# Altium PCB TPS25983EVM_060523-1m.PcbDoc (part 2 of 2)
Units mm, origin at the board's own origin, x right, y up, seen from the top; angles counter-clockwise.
Board outline 76.2 x 78.74 mm, 4 copper layers (L1-Top Layer, L2-GND1, L3-PWR/SIG, L4-Bottom Layer), stack 1.554 mm thick; 100 components, 38 nets, 213 pads, 280 vias.
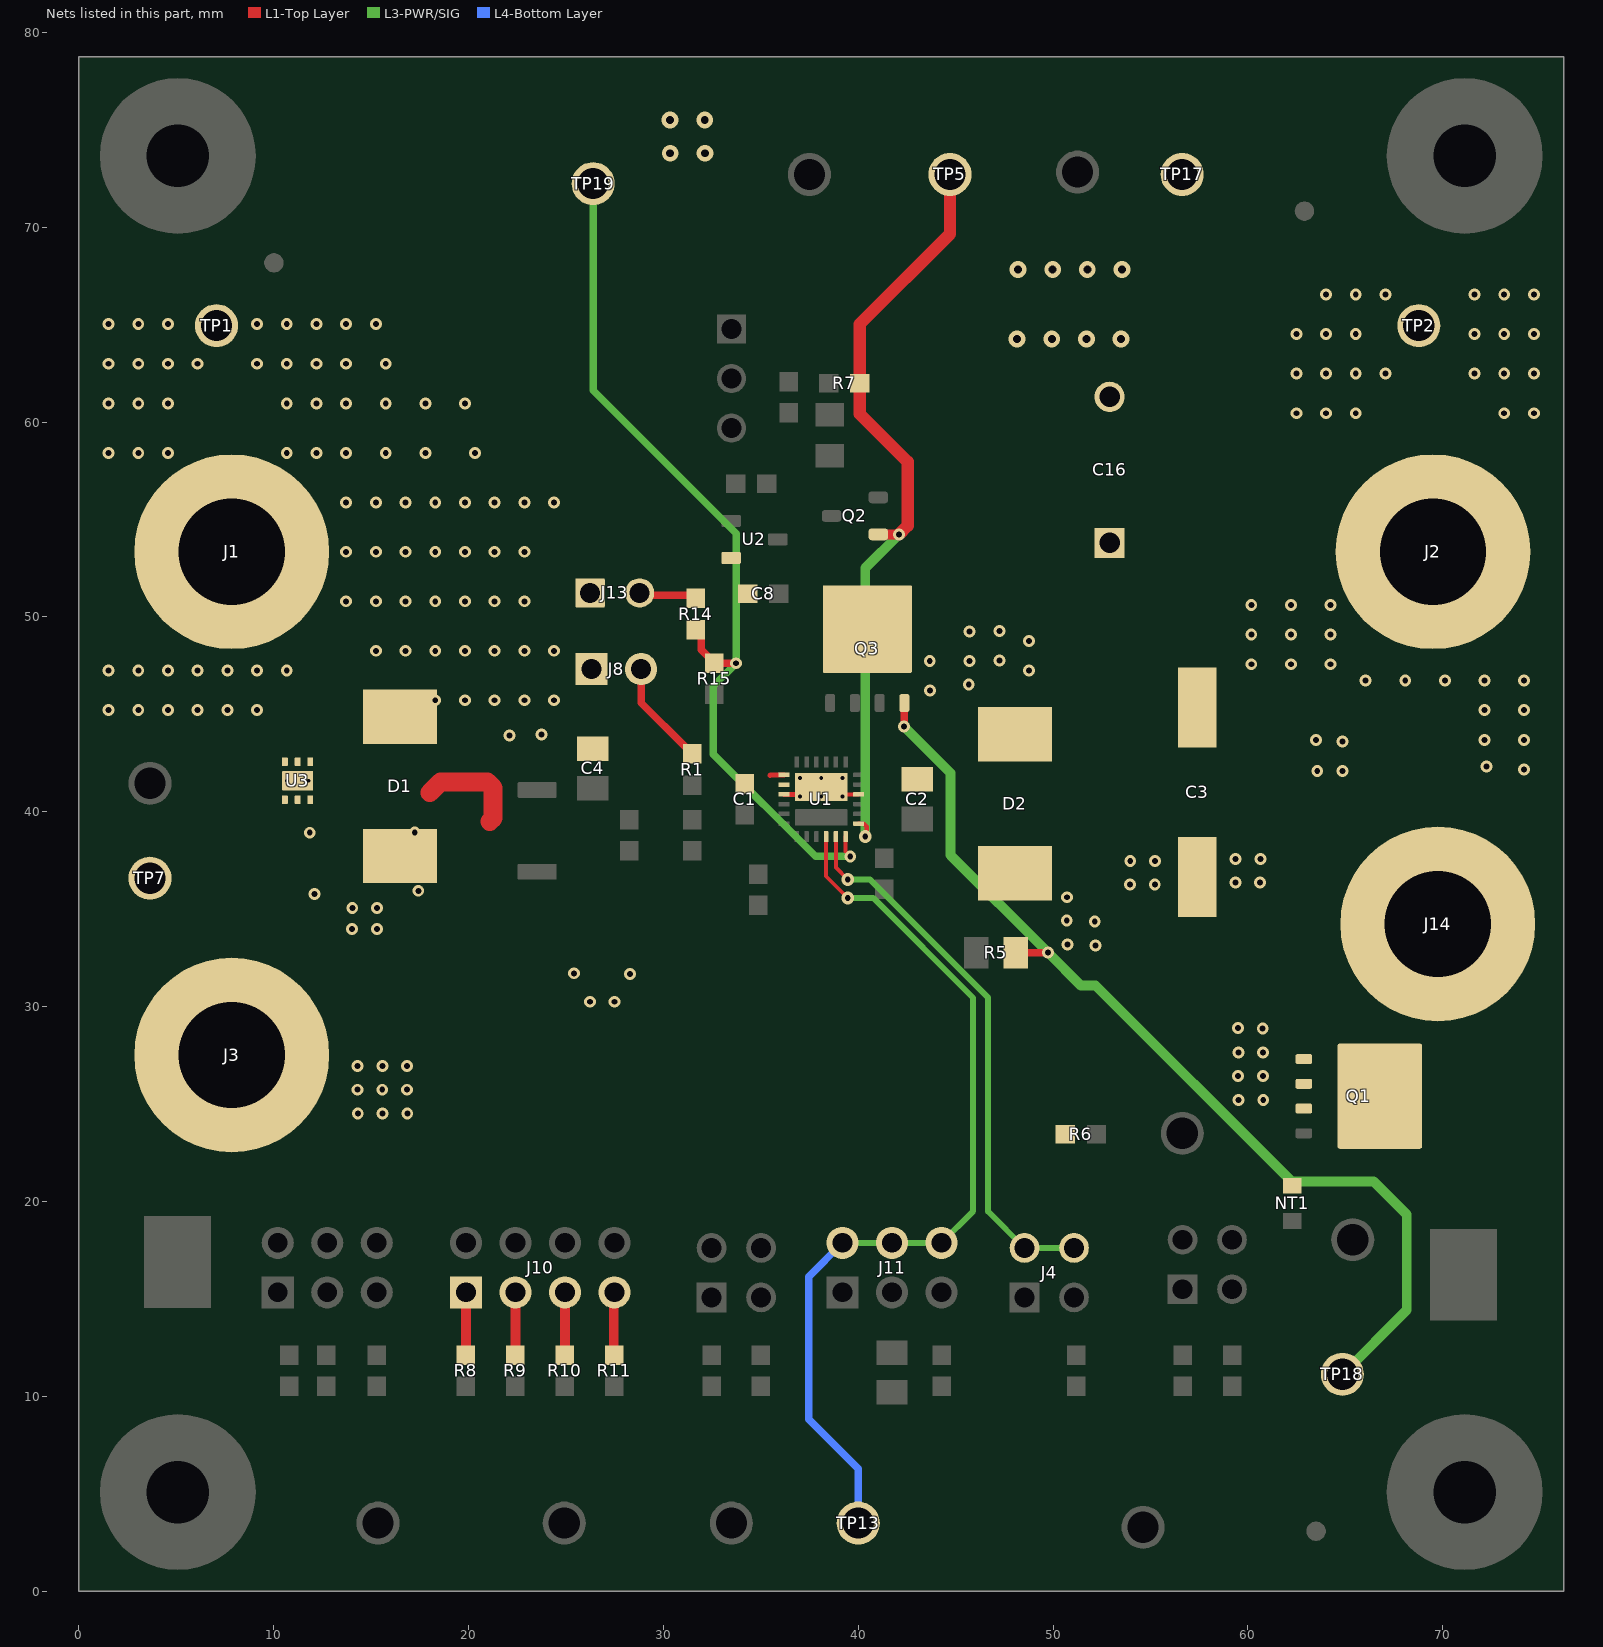
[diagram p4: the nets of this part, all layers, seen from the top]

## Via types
v1: diameter 0.61, hole 0.305, L1-Top Layer to L4-Bottom Layer, tented both sides, 249 vias
v2: diameter 0.864, hole 0.406, L1-Top Layer to L4-Bottom Layer, 12 vias
v3: diameter 0.5, hole 0.2, L1-Top Layer to L4-Bottom Layer, 11 vias
v4: diameter 0.66, hole 0.305, L1-Top Layer to L4-Bottom Layer, tented both sides, 8 vias

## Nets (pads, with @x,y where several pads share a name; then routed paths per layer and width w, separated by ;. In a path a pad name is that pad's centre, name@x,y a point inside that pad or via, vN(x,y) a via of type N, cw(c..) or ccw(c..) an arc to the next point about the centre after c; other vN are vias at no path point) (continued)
NetJ8_2: J8.2 R1.2 | length 5.5
  L1-Top Layer w0.381: J8.2@28.854,47.32 28.854,45.58 31.161,43.273 31.186,43.273 31.471,42.989 R1.2@31.471,42.964
NetJ10_1: J10.1 R8.2 | length 3.2
  L1-Top Layer w0.508: R8.2@19.864,12.108 J10.1@19.864,15.334
NetJ10_3: J10.3 R9.2 | length 3.5
  L1-Top Layer w0.508: R9.2@22.326,11.909 22.404,11.987 R9.2@22.404,12.108 J10.3@22.404,15.334
NetJ10_5: J10.5 R10.2 | length 3.1
  L1-Top Layer w0.508: J10.5@24.944,15.165 24.949,15.16 24.949,12.108 R10.2@24.949,12.079
NetJ10_7: J10.7 R11.2 | length 3.1
  L1-Top Layer w0.508: R11.2@27.448,12.079 27.448,12.108 27.448,15.129 J10.7@27.484,15.165
NetJ13_2: J13.2 R14.2 | length 3
  L1-Top Layer w0.381: J13.2@28.778,51.232 28.906,51.104 31.491,51.104 R14.2@31.648,50.947
NetJ14_1: J14.1 Q1.5 Q1.6 Q1.7 Q1.8 Q1.9
NetQ2_1: Q2.1 R7.1 TP5.1 U1.13 | length 39.9
  L1-Top Layer w0.229: U1.13@40.013,39.39 40.284,39.39 40.424,39.25 40.424,38.791 v4(40.357,38.724)
  L1-Top Layer w0.508: Q2.1@41.03,54.232 v1(42.086,54.232)
  L1-Top Layer w0.635: v1(42.086,54.232) 42.538,54.683 42.538,57.953 40.078,60.414 R7.1@40.078,61.981 40.078,65.024 44.707,69.653 TP5.1@44.707,72.707
  L3-PWR/SIG w0.508: v4(40.357,38.724) 40.357,52.503 v1(42.086,54.232)
NetQ3_4: Q3.4 R5.2 TP18.1 | length 51.1
  L1-Top Layer w0.381: v1@42.367,44.351 Q3.4@42.367,45.578 ; R5.2@48.082,32.766 v1(49.733,32.766)
  L3-PWR/SIG w0.508: v1(42.342,44.376) 44.729,41.988 44.729,37.77 v1(49.733,32.766) 51.416,31.083 52.184,31.083 62.236,21.031 66.446,21.031 68.148,19.329 68.148,14.427 TP18.1@64.846,11.125
NetR14_1: R14.1 R15.2 TP19.1 U1.12 | length 46.4
  L1-Top Layer w0.203: U1.12@39.35,38.727 39.35,37.95 v1(39.589,37.711)
  L1-Top Layer w0.381: R14.1@31.648,49.347 31.932,49.062 31.932,48.317 32.603,47.645 R15.2@32.603,47.62 v1(33.734,47.62)
  L3-PWR/SIG w0.381: TP19.1@26.391,72.238 26.391,61.62 33.734,54.277 v1(33.734,47.62) 32.566,46.452 32.566,42.949 37.803,37.711 v1(39.589,37.711)
NRETRY: J4.2 J4.4 U1.11 | length 28.3
  L1-Top Layer w0.203: U1.11@38.85,38.727 38.85,37.141 v4(39.46,36.53)
  L3-PWR/SIG w0.305: v4(39.46,36.53) 40.593,36.53 46.665,30.457 46.665,19.48 J4.2@48.533,17.612 J4.4@51.073,17.612
PGND: C3.2 C16.2 D1.2 D2.2 J3.1 NT1.2 Q1.1 Q1.2 Q1.3 R6.1 TP7.1 TP17.1 U3.1 U3.2 U3.3 U3.7@11.226,41.591 | length 5.4
  L1-Top Layer w0.965: 18.009,40.97 18.567,41.529 19.237,41.529 19.787,41.529 20.337,41.529 20.955,41.529 21.26,41.224 21.26,39.675 21.082,39.497
  other v1: 14.313,24.504 15.583,24.504 16.853,24.504 59.514,25.208 60.784,25.208 14.298,25.733 15.568,25.733 16.838,25.733 59.498,26.437 60.768,26.437 14.307,26.944 15.577,26.944 16.847,26.944 59.507,27.647 60.777,27.647 60.757,28.88 59.487,28.905 26.224,30.249 27.494,30.249 28.288,31.665 25.412,31.708 52.176,33.128 50.738,33.187 14.022,33.979 15.292,33.979 52.137,34.363 50.699,34.421 14.031,35.063 15.301,35.063 50.71,35.611 12.091,35.776 17.419,35.941 53.949,36.268 55.219,36.268 59.356,36.362 60.626,36.362 53.958,37.479 55.228,37.479 59.365,37.572 60.635,37.572 11.848,38.923 17.236,38.938
  other v2: 48.154,64.266 49.932,64.266 51.71,64.266 53.488,64.266 48.199,67.83 49.977,67.83 51.755,67.83 53.533,67.83 30.347,73.794 32.125,73.794 30.343,75.503 32.121,75.503
  other v3: 10.676,41.591 11.776,41.591
RETRY_DLY: J11.2 J11.4 J11.6 TP13.1 U1.10 | length 46.7
  L1-Top Layer w0.203: U1.10@38.35,38.727 38.35,36.688 v4(39.46,35.578)
  L3-PWR/SIG w0.305: J11.2@39.192,17.874 J11.4@41.732,17.874 J11.6@44.272,17.874 45.898,19.5 45.898,30.442 40.762,35.578 v4(39.46,35.578)
  L4-Bottom Layer w0.381: J11.2@39.192,17.874 37.455,16.136 37.455,8.825 39.999,6.28 TP13.1@39.999,3.49
VIN: C1.1 C4.1 C8.1 D1.1 J1.1 J8.1 J13.1 TP1.1 U1.1 U1.2 U1.3 U1.16 U1.25 U2.2 U3.4 U3.5 U3.6 | length 6.7
  L1-Top Layer w0.203: U1.25@38.861,40.89 U1.16@40.013,40.89
  L1-Top Layer w0.254: 35.458,41.859 35.489,41.89 U1.1@36.187,41.89 ; U1.3@36.187,40.89 37.725,40.89 U1.25@38.1,41.265 ; U1.25@36.93,41.265 U1.25@38.1,41.265 ; U1.25@36.937,41.758 37.607,41.758 U1.25@38.1,41.265 ; U1.25@38.735,41.016 U1.25@38.861,40.89
  other v1: 22.098,43.917 23.749,43.967 1.524,45.212 3.048,45.212 4.572,45.212 6.096,45.212 7.62,45.212 9.144,45.212 18.288,45.72 19.812,45.72 21.336,45.72 22.86,45.72 24.384,45.72 1.524,47.244 3.048,47.244 4.572,47.244 6.096,47.244 7.62,47.244 9.144,47.244 10.668,47.244 15.24,48.26 16.764,48.26 18.288,48.26 19.812,48.26 21.336,48.26 22.86,48.26 24.384,48.26 13.716,50.8 15.24,50.8 16.764,50.8 18.288,50.8 19.812,50.8 21.336,50.8 22.86,50.8 13.716,53.34 15.24,53.34 16.764,53.34 18.288,53.34 19.812,53.34 21.336,53.34 22.86,53.34 13.716,55.88 15.24,55.88 16.764,55.88 18.288,55.88 19.812,55.88 21.336,55.88 22.86,55.88 24.384,55.88 1.524,58.42 3.048,58.42 4.572,58.42 10.668,58.42 12.192,58.42 13.716,58.42 15.748,58.42 17.78,58.42 20.32,58.42 1.524,60.96 3.048,60.96 4.572,60.96 10.668,60.96 12.192,60.96 13.716,60.96 15.748,60.96 17.78,60.96 19.812,60.96 1.524,62.992 3.048,62.992 4.572,62.992 6.096,62.992 9.144,62.992 10.668,62.992 12.192,62.992 13.716,62.992 15.748,62.992 1.524,65.024 3.048,65.024 4.572,65.024 9.144,65.024 10.668,65.024 12.192,65.024 13.716,65.024 15.24,65.024
  other v3: 37,40.79 38.1,40.79 39.2,40.79 37,41.74 38.1,41.74 39.2,41.74
VOUT: C2.1 C3.1 C16.1 D2.1 J2.1 Q3.5 Q3.6 Q3.7 Q3.8 Q3.9 TP2.1
  other v1: 64.846,42.088 63.555,42.099 74.168,42.164 72.234,42.313 64.846,43.612 63.5,43.688 72.136,43.688 74.168,43.688 72.136,45.212 74.168,45.212 43.688,46.228 45.669,46.533 66.04,46.736 68.072,46.736 70.104,46.736 72.136,46.736 74.168,46.736 48.768,47.244 60.172,47.57 62.204,47.57 64.236,47.57 43.667,47.728 45.699,47.728 47.244,47.752 48.768,48.768 60.172,49.094 62.204,49.094 64.236,49.094 45.699,49.252 47.244,49.276 60.172,50.618 62.204,50.618 64.236,50.618 62.484,60.452 64.008,60.452 65.532,60.452 73.152,60.452 74.676,60.452 62.484,62.484 64.008,62.484 65.532,62.484 67.056,62.484 71.628,62.484 73.152,62.484 74.676,62.484 62.484,64.516 64.008,64.516 65.532,64.516 71.628,64.516 73.152,64.516 74.676,64.516 64.008,66.548 65.532,66.548 67.056,66.548 71.628,66.548 73.152,66.548 74.676,66.548
pads on no net: FID1.1 FID2.1 FID3.1 H1.1 H2.1 H3.1 H4.1 H5.0 H6.0 H7.0 H8.0 SH-J1.0 SH-J2.0 SH-J3.0 SH-J4.0 SH-J5.0 SH-J6.0 SH-J7.0 U3.7@10.776,41.591 U3.7@11.676,41.591

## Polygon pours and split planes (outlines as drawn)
PGND on L1-Top Layer "L1-TOP_LAYER_PGND_P100" (solid, remove dead copper, pour order 100): 64.153,68.459 48.095,52.401 39.334,52.401 37.784,53.952 37.784,58.635 36.221,60.198 22.885,60.198 14.834,68.326 2.094,68.284 0.864,69.514 0.864,73 5.639,77.749 10.338,77.749 71.196,77.749 75.558,73.388 75.558,69.593 74.424,68.459
PGND on L1-Top Layer "L1-TOP_LAYER_PGND_P098" (solid, remove dead copper, pour order 98): 2.646,20.389 1.055,21.981 1.055,41.14 1.437,41.545 21.793,41.545 21.793,33.463 23.023,32.233 43.885,32.233 44.876,33.223 44.876,40.044 45.15,40.339 63.437,40.339 64.016,39.757 64.016,21.07 63.386,20.389
NetJ14_1 on L1-Top Layer "NONET_L01_P-001" (solid, pour order 125): 64.57,20.253 64.57,39.32 65.681,40.431 74.195,40.431 75.686,38.94 75.686,21.429 74.371,20.114 64.709,20.114
GND on L1-Top Layer "L1-TOP_LAYER_GND_P092" (solid, remove dead copper, pour order 92): 61.476,19.593 61.666,19.403 62.954,19.403 63.142,19.593 69.345,19.593 72.436,19.593 74.286,19.593 75.526,18.391 75.526,9.107 75.526,6.904 68.961,0.432 6.147,0.432 0.7,5.879 0.734,10.008 0.734,14.915 0.715,18.158 2.15,19.593
GND on L1-Top Layer "L1-TOP_LAYER_GND_P088" (solid, remove dead copper, pour order 88): 33.167,40.514 32.598,39.945 32.609,39.391 31.804,38.586 27.584,38.586 27.229,38.941 27.229,41.758 27.127,41.859 25.552,41.859 25.326,41.633 25.326,38.989 24.92,38.586 22.428,38.586 22.428,33.68 23.241,32.868 43.544,32.868 44.174,33.498 44.174,40.213 44.042,40.335 42.871,40.335 36.703,40.335 36.524,40.514
VIN on L1-Top Layer "L1-TOP_LAYER_VIN_P090" (solid, remove dead copper, pour order 90): 33.432,53.83 32.996,53.83 32.147,54.678 32.147,55.115 32.147,57.444 30.501,59.09 22.647,59.09 13.79,67.947 1.488,67.947 1.087,67.474 1.087,43.179 1.975,42.291 32.026,42.291 32.183,42.134 32.183,41.404 32.352,41.235 35.878,41.235 35.878,48.668 35.878,49.686 34.865,50.699 34.865,52.397 34.112,53.15
GND on L1-Top Layer "M1 Board Outline-No Net" (solid, pour order 104): 34.591,54.129 35.463,53.258 35.463,50.781 35.613,50.63 36.635,50.63 37.02,51.015 37.02,57.672 36.712,57.979 35.216,57.979 34.941,57.979 34.591,57.629
DVOUT on L1-Top Layer "NONET_L-01_P-001" (solid, remove dead copper, pour order 121): 41.187,46.154 37.639,46.154 36.512,45.027 36.512,42.497 36.743,42.266 39.496,42.266 39.719,42.043 39.719,41.258 39.766,41.211 40.248,41.211 40.326,41.289 40.326,42.934 41.371,43.979 41.371,45.97
VOUT on L1-Top Layer "L1-TOP_LAYER_VOUT_P086" (solid, remove dead copper, pour order 86): 41.69,42.801 43.34,44.451 43.34,46.673 42.914,47.099 38.255,47.099 37.614,47.74 37.614,51.061 38.144,51.591 48.361,51.591 64.534,67.765 74.694,67.765 75.123,67.365 75.123,42.338 73.808,41.023 42.062,41.023 41.69,41.395
PGND on L4-Bottom Layer "PWR1-No Net" (solid, pour order 114): 1.025,73.694 1.025,5.668 6.007,0.686 69.977,0.686 75.408,6.117 75.408,73.605 70.759,78.254 5.584,78.254
VIN on L4-Bottom Layer "L4-BOTTOM_LAYER_VIN_P106" (solid, remove dead copper, pour order 106): 29.128,52.89 14.2,67.818 1.016,67.818 1.016,40.564 39.377,40.564 39.498,40.684 39.498,40.964 39.498,41.604 39.498,46.388 32.995,52.89
GND on L4-Bottom Layer "M1 Board Outline-No Net" (solid, pour order 112): 39.471,39.935 39.813,39.593 39.813,38.223 40.529,37.507 40.529,34.372 38.956,32.788 24.303,32.788 23.58,33.512 23.58,39.332 24.165,39.917 36.842,39.917 36.861,39.935
VOUT on L4-Bottom Layer "GND_L01_P-001" (solid, remove dead copper, pour order 110): 41.656,45.665 41.656,49.922 42.438,50.673 47.427,50.673 49.906,48.194 49.906,42.447 49.191,41.732 45.589,41.732
PGND on L3-PWR/SIG "NONET_L-01_P-001" (solid, remove dead copper, pour order 123): 40.61,61.121 40.61,55.442 40.985,55.067 46.783,55.067 47.972,56.256 58.046,56.256 60.361,58.571 60.361,61.866 57.128,65.099 57.128,68.582 59.902,71.356 59.902,74.985 59.11,75.778 54.834,75.778 54.062,75.006 54.062,70.897 52.227,69.062 48.551,69.062
VOUT on L3-PWR/SIG "PWR1-No Net" (solid, pour order 108): 58.365,55.118 48.136,55.118 43.27,50.253 43.27,44.668 46.773,41.148 73.939,41.148 75.184,42.393 75.184,66.726 72.72,69.19 58.903,69.19 57.988,68.275 57.988,65.456 61.354,62.09 61.354,58.108
DVOUT on L3-PWR/SIG "NONET_L-01_P-001" (solid, remove dead copper, pour order 122): 53.332,74.203 51.655,75.88 44.701,75.88 34.851,66.03 34.851,43.797 35.894,42.754 39.085,42.754 39.559,43.227 39.559,61.612 48.239,70.292 52.542,70.292 53.332,71.082
VIN on L3-PWR/SIG "PWR1-No Net" (solid, remove dead copper, pour order 116): 15.176,66.459 1.892,66.459 1.118,65.684 1.118,41.072 1.651,40.538 26.695,40.538 27.483,41.326 27.483,54.153 21.949,59.687
GND on L2-GND1 "PWR1-No Net" (solid, remove dead copper, pour order 120): 6.649,1.041 0.991,6.699 1.025,7.391 1.025,74.101 5.178,78.254 70.759,78.254 75.408,73.605 75.408,6.879 69.571,1.041

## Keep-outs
Keep-Out Layer:
  lines w0.254: 0,0 76.2,0 ; 0,0 0,78.74 ; 0,0 76.2,0 ; 0,0 0,78.74 ; 0,78.74 76.2,78.74 ; 0,78.74 76.2,78.74 ; 76.2,0 76.2,78.74
  text ".Layer_Name" at 9.082,-28.565 h1.52

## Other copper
L1-Top Layer:
  region net GND: 62.96,19.403 61.666,19.403 61.574,19.311 61.574,18.7 61.678,18.596 62.902,18.596 63.009,18.703 63.009,19.354
  region net PGND: 61.599,20.389 62.893,20.389 62.985,20.481 62.985,21.092 62.88,21.196 61.657,21.196 61.549,21.089 61.549,20.439
  region net VIN: 32.183,42.42 32.599,42.836 35.65,42.836 36.529,41.957 39.225,41.957 39.314,41.868 39.314,40.904 39.075,40.665 37.059,40.665 36.957,40.767 32.769,40.767 32.183,41.354
  region net DVOUT: 36.677,42.98 36.806,43.109 39.909,43.109 40.326,42.692 40.326,41.289 40.248,41.211 39.766,41.211 39.719,41.258 39.719,42.043 39.496,42.266 36.743,42.266 36.677,42.332
  region net DVDT: 40.97,40.259 41.097,40.132 41.097,38.329 40.843,38.075 40.843,37.135 40.894,37.084 41.758,37.084 41.808,37.135 41.808,38.176 41.681,38.303 41.681,40.894 41.554,41.021 41.173,41.021 40.665,40.513 39.751,40.513 39.726,40.488 39.726,40.284 39.751,40.259
  region net GND: 35.89,40.513 35.814,40.437 35.814,39.878 35.916,39.776 36.652,39.776 36.754,39.675 36.754,39.319 36.779,39.294 39.421,39.294 39.472,39.345 39.472,39.7 39.548,39.776 40.284,39.776 40.31,39.802 40.31,39.98 40.259,40.03 39.548,40.03 39.421,40.157 36.881,40.157 36.525,40.513
  pour cut-out: 34.612,36.565 35.233,35.944 40.185,35.944 40.533,35.944 41.17,36.582 41.17,38.285 40.245,39.21 40.184,39.149 35.27,39.149 34.612,38.491
  text ".Layer_Name" at 9.082,-28.565 h1.52
L2-GND1:
  text ".Layer_Name" at 9.057,-28.615 h1.52
L3-PWR/SIG:
  text ".Layer_Name" at 9.082,-28.615 h1.52
L4-Bottom Layer:
  text ".Layer_Name" at 9.082,-28.565 h1.52

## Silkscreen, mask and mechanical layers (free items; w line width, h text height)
Top Overlay:
  circle w0.254: c35.963,42.405 r0.085
  circle w0.254: c22.071,41.414 r0.085
  lines w0.127: 10.389,41.626 10.77,41.626 ; 12.834,36.676 13.596,36.676 13.215,36.676 ; 13.215,35.914 13.215,36.295 ; 13.215,37.057 13.215,36.676 ; 40.348,58.205 40.348,58.586 ; 40.348,58.967 40.348,59.348 ; 40.509,57.994 40.666,57.994 ; 40.512,58.148 40.666,57.994 ; 40.666,58.151 40.666,57.994 ; 40.729,58.586 39.967,58.586 40.348,58.586 ; 40.777,58.265 40.933,58.265 ; 40.779,58.418 40.933,58.265 ; 40.933,58.421 40.933,58.265 ; 45.031,35.375 45.793,35.375 45.412,35.375 ; 45.412,34.613 45.412,34.994 ; 45.412,35.756 45.412,35.375 ; 13.215,36.676 12.834,36.295 13.596,36.295 13.215,36.676 ; 40.348,58.586 40.729,58.967 39.967,58.967 40.348,58.586 ; 45.412,35.375 45.031,34.994 45.793,34.994 45.412,35.375
  lines w0.152: 30.328,34.666 30.328,43.701 31.041,44.414 33.898,44.414 44.006,44.414 44.401,44.019 44.401,34.376 44.111,34.087 30.907,34.087 30.328,34.666
  text "PGND" at 55.06,75.14 h0.89
  text "OVLO" at 28.949,70.249 h0.76
  text "VOUT" at 66.709,60.127 h1.52
  text "VIN" at 5.293,59.913 h1.52
  text "18A MAX DC" at 11.079,56.25 h1.52
  text "VIN_OVLO" at 22.594,53.479 h0.76
  text "VIN_UVLO" at 22.432,44.63 h0.76
  text "EN/UVP" at 1.142,43.621 h0.89
  text "PGND" at 5.41,33.154 h1.27
  text "P-LOAD" at 63.648,29.691 h0.89 r90
  text "'.PRJ_Title'" at 31.857,27.674 h1.52
  text "PLOAD_ON" at 49.567,25.934 h1.52
  text "Caution Hot surface. / Contact may cause burns.  / Do not touch!" at 12.65,22.44 h1.52
  text "DVDT" at 64.009,20.37 h0.89
  text "GND" at 3.759,20.117 h0.89
  text "GND" at 69.818,19.518 h0.89
  text "GATE" at 62.397,6.369 h0.89
  text "TIMER" at 13.335,5.74 h0.89
  text "ILIM" at 23.52,5.74 h0.89
  text "IMON" at 31.979,5.715 h0.89
  text "NRETRY" at 46.369,5.572 h0.89
  text "GND" at 53.085,5.572 h0.89
  text "RETRY_DLY" at 36.373,5.537 h0.89
  text ".Layer_Name" at 9.082,-28.565 h1.52
Bottom Overlay:
  text ".Layer_Name" at 9.082,-28.565 h1.52
Top Paste:
  text ".Layer_Name" at 9.082,-28.565 h1.52
Bottom Paste:
  text ".Layer_Name" at 9.082,-28.565 h1.52
Top Solder:
  text ".Layer_Name" at 9.082,-28.565 h1.52
  text ".Layer_Name" at 9.082,-28.565 h1.52
Bottom Solder:
  text ".Layer_Name" at 9.082,-28.565 h1.52
Drill Guide:
  text ".Layer_Name" at 9.082,-28.565 h1.52
M1 Board Outline:
  the board outline again, w0.254
  text ".Layer_Name" at 9.082,-28.565 h1.52
M2 Board Dimensions:
  rectangle: -2.398,-16.919 7.127,-13.744
  rectangle: -5.573,-13.744 -2.398,-10.569
  lines w0.178: -5.573,-13.744 19.827,-13.744 ; -2.398,-16.919 -2.398,-10.569 ; 0.777,-16.919 0.777,-10.569 ; 7.127,-16.919 7.127,-10.569 ; 13.477,-16.919 13.477,-10.569 ; -5.573,-16.919 -5.573,-10.569 19.827,-10.569 19.827,-16.919 -5.573,-16.919
  text ".Layer_Name" at 9.082,-28.565 h1.52
M3 3D STEP Top:
  text ".Layer_Name" at 9.082,-28.565 h1.52
M4 3D STEP Bottom:
  text ".Layer_Name" at 9.082,-28.565 h1.52
M5 Assembly Top:
  circle w0.508: c54.617,11.566 r0.172
  circle w0.508: c31.977,57.662 r0.172
  circle w0.508: c22.488,41.428 r0.172
  lines w0.254: -12.99,-30.385 154.65,-30.385 ; -12.99,-25.22 154.701,-25.22 ; -12.99,-20.056 -12.99,-35.55 88.737,-35.55 154.701,-35.55 154.701,-20.056 -12.978,-20.056 -12.978,-35.55 27.04,-35.55 ; 49.621,-35.55 49.621,-20.056 ; 81.803,-25.22 81.803,-20.056 ; 103.139,-25.22 103.139,-20.056 ; 118.937,-35.715 118.937,-30.563
  text "COMPONENTS MARKED 'DNP' SHOULD NOT BE POPULATED." at 23.725,-14.849 h1.52
  text "ASSEMBLY VARIANT:" at 23.713,-17.782 h1.52
  text ".VariantName" at 50.027,-17.782 h1.52
  text "PCB VIEWED FROM TOP SIDE" at -11.377,-23.413 h1.52
  text "BOARD #:" at 51.526,-23.413 h1.52
  text ".PRJ_Number" at 65.381,-23.413 h1.52
  text "REV:" at 86.832,-23.413 h1.52
  text ".PCB_Rev" at 94.236,-23.413 h1.52
  text "SVN REV:" at 108.117,-23.413 h1.52
  text ".VersionControl_RevNumber" at 120.969,-23.413 h1.52
  text "TID #:" at 51.526,-28.577 h1.52
  text ".TID" at 65.381,-28.577 h1.52
  text "PLOT NAME =" at -11.377,-33.793 h1.52
  text ".plot_File_Name" at 9.082,-33.793 h1.52
  text "GENERATED    :" at 51.577,-33.793 h1.52
  text ".Print_Date" at 73.662,-33.793 h1.52
  text ".Print_Time" at 92.178,-33.793 h1.52
  text "TEXAS INSTRUMENTS" at 124.297,-33.793 h1.52
M6 Assembly Bottom:
  lines w0.254: -13.003,-25.233 154.688,-25.233 ; -12.952,-30.398 154.688,-30.398 ; 22.76,-35.727 22.76,-30.576 ; 38.559,-25.233 38.559,-20.068 ; 59.895,-25.233 59.895,-20.068 ; 92.077,-35.562 92.077,-20.068 ; 114.657,-35.562 154.675,-35.562 154.675,-20.068 -13.003,-20.068 -13.003,-35.562 52.961,-35.562 154.688,-35.562 154.688,-20.068
  text "COMPONENTS MARKED 'DNP' SHOULD NOT BE POPULATED." at 149.417,-14.836 h1.52
  text ".VariantName" at 122.9,-17.782 h1.52
  text "ASSEMBLY VARIANT:" at 149.29,-17.782 h1.52
  text ".VersionControl_RevNumber" at 20.728,-23.425 h1.52
  text "SVN REV:" at 33.581,-23.425 h1.52
  text ".PCB_Rev" at 47.462,-23.425 h1.52
  text "REV:" at 54.866,-23.425 h1.52
  text ".PRJ_Number" at 76.316,-23.425 h1.52
  text "BOARD #:" at 90.172,-23.425 h1.52
  text "PCB VIEWED FROM BOTTOM SIDE" at 153.075,-23.425 h1.52
  text ".TID" at 76.316,-28.59 h1.52
  text "TID #:" at 90.172,-28.59 h1.52
  text "TEXAS INSTRUMENTS" at 17.401,-33.806 h1.52
  text ".Print_Time" at 49.519,-33.806 h1.52
  text ".Print_Date" at 68.036,-33.806 h1.52
  text "GENERATED    :" at 90.121,-33.806 h1.52
  text ".plot_File_Name" at 132.615,-33.806 h1.52
  text "PLOT NAME =" at 153.075,-33.806 h1.52
M9 Title Sheet:
  drawing of 57 lines, arcs and shapes, not listed
  text "1" at 13.218,197.368 h1.78
  text "2" at 76.608,197.368 h1.78
  text "3" at 139.838,197.368 h1.78
  text "4" at 203.507,197.368 h1.78
  text "5" at 266.981,197.368 h1.78
  text "6" at 330.608,197.368 h1.78
  text "A" at -16.153,168.336 h1.78
  text "A" at 359.767,168.336 h1.78
  text "B" at -16.153,107.884 h1.78
  text "B" at 359.767,107.884 h1.78
  text "C" at -16.153,47.559 h1.78
  text "C" at 359.767,47.559 h1.78
  text "PROJECT TITLE:" at 282.551,0.29 h1.14
  text ".PRJ_Title" at 283.821,-3.097 h1.78
  text "DESIGNED FOR:" at 282.551,-7.356 h1.14
  text ".PRJ_Customer" at 283.821,-10.912 h1.78
  text "D" at -16.153,-12.639 h1.78
  text "D" at 359.767,-12.639 h1.78
  text "FILE NAME:" at 282.551,-14.976 h1.14
  text ".PCB_File_Name_No_Path" at 283.821,-18.024 h1.78
  text "Texas Instruments (TI) and/or its licensors do not warrant the accuracy or completeness of this specification" at 156.326,-22.134 h1.14
  text "ENGINEER:" at 282.551,-22.342 h1.14
  text "LAYOUT BY:" at 320.778,-22.342 h1.14
  text "or any information contained therein. TI and/or its licensors do not warrant that this design will meet" at 155.184,-24.996 h1.14
  text ".PRJ_Engineer" at 283.821,-26.279 h1.78
  text ".PCB_Layout" at 322.061,-26.279 h1.78
  text "the specifications, will be suitable for your application or fit for any particular purpose, or will operate in" at 155.184,-27.858 h1.14
  text ".Layer_Name" at 9.082,-28.565 h1.52
  text "ALTIUM DESIGNER VERSION:" at 320.778,-30.216 h1.14
  text "an implementation. TI and/or its licensors do not warrant that the design is production worthy. You should" at 155.184,-30.719 h1.14
  text "completely validate and test your design implementation to confirm the system functionality for your application." at 156.326,-33.581 h1.14
  text ".print_Scale" at 283.821,-33.602 h1.78
  text ".Application_BuildNumber" at 322.061,-33.602 h1.78
  text "1" at 13.218,-38.852 h1.78
  text "2" at 76.608,-38.852 h1.78
  text "3" at 139.838,-38.852 h1.78
  text "4" at 203.507,-38.852 h1.78
  text "5" at 266.981,-38.852 h1.78
  text "6" at 330.608,-38.852 h1.78
M10 Fab Notes:
  drawing of 189 lines, arcs and shapes, not listed
  text "DESIGN INFORMATION" at 308.93,154.688 h1.52
  text "MIN. TRACK WIDTH:" at 292.558,151.332 h1.52
  text "8" at 320.403,151.332 h1.52
  text "MIL" at 324.333,151.332 h1.52
  text "MIN. CLEARANCE:" at 292.558,148.179 h1.52
  text "7" at 320.37,148.184 h1.52
  text "MIL" at 324.333,148.179 h1.52
  text "MIN. VIA PAD SIZE:" at 292.558,145.026 h1.52
  text "MIL" at 324.333,145.026 h1.52
  text "19.68" at 316.967,144.856 h1.52
  text "0.05mm (2MIL)" at 310.211,141.727 h1.52
  text "MINIMUM ANNULAR RING" at 284.196,141.518 h1.52
  text "EXTERNAL" at 328.194,141.518 h1.52
  text "PER" at 289.276,138.721 h1.52
  text "IPC-D-275 CLASS 2 LEVEL C" at 294.864,138.721 h1.52
  text "MIL, HOLES" at 332.665,136.169 h1.52
  text "+/-" at 322.696,135.951 h1.52
  text "+/-" at 344.388,135.951 h1.52
  text "REGISTRATION TOLERANCES:" at 284.196,135.924 h1.52
  text "METAL" at 314.67,135.924 h1.52
  text "5" at 329.305,135.924 h1.52
  text "3" at 350.464,135.924 h1.52
  text "MIL" at 353.416,135.924 h1.52
  text "HOLE SIZE TOLERANCE (UNLESS OTHERWISE SPECIFIED):" at 284.196,133.426 h1.52
  text "+/-" at 344.388,133.353 h1.52
  text "3" at 350.464,133.327 h1.52
  text "MIL" at 353.416,133.326 h1.52
  text "MATERIAL:" at 282.296,129.83 h1.52
  text "FR-4 High Tg" at 307.352,126.566 h1.52
  text "X" at 303.683,126.363 h1.52
  text "FR-408" at 292.99,126.248 h1.52
  text "OTHER" at 330.785,126.248 h1.52
  text "X" at 298.07,122.553 h1.52
  text "62MIL (1.6mm) +/-10%" at 300.66,122.479 h1.52
  text "THICKNESS:" at 284.196,122.406 h1.52
  text "OTHER" at 333.757,122.406 h1.52
  text "TOLERANCE:" at 284.196,118.893 h1.52
  text "X" at 305.741,118.893 h1.52
  text "ANSI IPC-6012 TYPE 3 CLASS 2" at 310.262,118.893 h1.52
  text "OTHER +/-" at 310.262,115.231 h1.52
  text "Fab notes:" at -1.583,115.008 h3.81
  text "BOW & TWIST:" at 284.196,111.543 h1.52
  text "X" at 305.741,111.543 h1.52
  text "ANSI IPC-6012 TYPE 3 CLASS 2" at 310.262,111.543 h1.52
  text "1.NO VENDOR LOGO OR NAME ON THE BOARD." at -1.71,110.515 h1.91
  text "OTHER +/-" at 310.262,107.817 h1.52
  text "2.ALL HOLES SHOULD BE FHS." at -1.71,106.023 h1.91
  text "DRILLING:" at 282.296,104.499 h1.52
  text "NC_DRILL FILES" at 327.026,101.827 h1.52
  text "REFERENCE:" at 284.196,101.727 h1.52
  text "X" at 300.889,101.725 h1.52
  text "AS SHOWN" at 305.41,101.727 h1.52
  text "X" at 323.775,101.727 h1.52
  text "3.NEED TO REMOVE THE NON FUNCTIONAL PADS IN INNER LAYERS." at -1.71,101.531 h1.91
  text "OTHER" at 334.595,98.114 h1.52
  text "PTH COPPER THICKNESS:" at 284.187,98.024 h1.52
  text "X" at 313.124,98.024 h1.52
  text "20-30 um" at 316.375,98.024 h1.52
  text "4.CLIP SILKSCREEN ON NO MASK AREA." at -1.71,97.245 h1.91
  text "BOARD FINISH:" at 282.296,94.275 h1.52
  text "5.ALL 7.87MIL DRILLS NEED TO BE NON-CONDUCTIVE VIA PLUGGING FROM BOTTOM SIDE." at -1.71,92.753 h1.91
  text "SILKSCREEN:" at 286.239,91.478 h1.52
  text "X" at 310.567,91.478 h1.52
  text "TOP" at 313.538,91.478 h1.52
  text "BOTTOM" at 326.518,91.478 h1.52
  text "SILKSCREEN COLOR:" at 286.239,87.536 h1.52
  text "X" at 310.541,87.536 h1.52
  text "WHITE" at 313.538,87.536 h1.52
  text "OTHER" at 326.518,87.536 h1.52
  text "X" at 313.869,83.893 h1.52
  text "GREEN" at 316.866,83.893 h1.52
  text "OTHER" at 332.563,83.893 h1.52
  text "SOLDER RESIST COLOR:" at 286.239,83.718 h1.52
  text "X" at 313.869,79.975 h1.52
  text "MATTE" at 316.866,79.975 h1.52
  text "SEMI-GLOSS" at 332.551,79.959 h1.52
  text "IMMERSION GOLD (ENIG)" at 309.246,75.586 h1.52
  text "ENEPIG" at 343.219,75.403 h1.52
  text "SURFACE FINISH:" at 282.296,75.378 h1.52
  text "X" at 304.725,75.378 h1.52
  text "IMM. TIN/SILVER OR EQUIV" at 290.667,71.89 h1.52
  text "OTHER" at 327.026,71.79 h1.52
  text "ARRAY/PANEL:" at 282.296,67.843 h1.52
  text "X" at 304.622,67.691 h1.52
  text "CUT AND TRIM PER M1 BOARD OUTLINE" at 309.246,67.634 h1.52
  text "N.C. ROUTE" at 309.246,64.181 h1.52
  text "V. SCORE" at 331.242,64.181 h1.52
  text "CERTIFICATION:" at 282.296,60.901 h1.52
  text "MATERIALS AND WORKMANSHIP FOR ALL PCBS" at 300.711,60.901 h1.52
  text "TO MEET OR EXCEED THE REQUIREMENTS OF:" at 300.711,58.512 h1.52
  text "X" at 291.504,55.245 h1.52
  text "ANSI IPC-A-600F CLASS ->" at 294.755,55.245 h1.52
  text "X" at 336.615,55.245 h1.52
  text "2" at 339.408,55.245 h1.52
  text "1" at 331.407,55.207 h1.52
  text "3" at 348.4,55.207 h1.52
  text "X" at 312.129,51.493 h1.52
  text "RoHS" at 315.38,51.493 h1.52
  text "OTHER" at 331.748,51.493 h1.52
  text "PER ORDER" at 341.833,51.493 h1.52
  text "ALL BOARDS MUST MEET OR EXCEED UL94-V0 REQUIREMENTS." at 282.996,47.586 h1.52
  text "PCB MUST BEAR THE UL94V-0 UL REGISTERED MATERIAL ID NUMBER" at 282.996,44.638 h1.52
  text "ADDITIONAL REQUIREMENTS:" at 282.296,40.335 h1.52
  text "MICROSECTION:" at 284.196,37.614 h1.52
  text "YES" at 307.201,37.614 h1.52
  text "REQUIRED" at 329.083,33.948 h1.52
  text "BARE BOARD ELEC. TEST:" at 284.196,33.875 h1.52
  text "NONE" at 317.361,33.875 h1.52
  text "X" at 326.086,33.875 h1.52
  text "PER ORDER" at 344.12,33.875 h1.52
  text "XX MIL VIAS REQUIRE NON-CONDUCTIVE FILL AND PLANARIZE" at 288.467,28.67 h1.5
  text "ALL 7.87 AND 12 MIL VIAS REQUIRE TENTING ON BOTH SIDES" at 288.67,26.029 h1.52
  text "X" at 285.699,25.908 h1.52
  text "OUTER XX MIL TRACES REQUIRE 50 OHM SINGLE-ENDED IMPEDANCE" at 288.645,21.879 h1.45
  text "LAYER 2 & 3 (INNER LAYERS) XX MIL WIDE, XX MIL SPACE / TRACES REQUIRE 100 OHM DIFFERENTIAL IMPEDANCE" at 288.442,15.892 h1.52
  text ".Layer_Name" at 9.082,-28.565 h1.52
M11 Gerber Information:
  lines w0.254: -12.99,-30.385 154.65,-30.385 ; -12.99,-25.22 154.701,-25.22 ; -12.99,-20.056 -12.99,-35.55 88.737,-35.55 154.701,-35.55 154.701,-20.056 -12.978,-20.056 -12.978,-35.55 27.04,-35.55 ; 49.621,-32.775 49.621,-20.056 ; 81.803,-25.22 81.803,-20.056 ; 103.139,-25.22 103.139,-20.056 ; 118.937,-35.715 118.937,-30.563
  text "ALL ARTWORK VIEWED FROM TOP SIDE" at -11.377,-23.413 h1.52
  text "BOARD #:" at 51.526,-23.413 h1.52
  text "REV:" at 86.832,-23.413 h1.52
  text ".PCB_Rev" at 94.236,-23.413 h1.52
  text "SVN REV:" at 108.117,-23.413 h1.52
  text ".VersionControl_RevNumber" at 120.969,-23.413 h1.52
  text "LAYER NAME =" at -11.377,-28.565 h1.52
  text "TID #:" at 51.526,-28.577 h1.52
  text ".TID" at 65.381,-28.577 h1.52
  text "PLOT NAME =" at -11.377,-33.793 h1.52
  text "GENERATED    :" at 57.37,-33.827 h1.52
  text ".Print_Date" at 79.455,-33.827 h1.52
  text ".Print_Time" at 97.972,-33.827 h1.52
  text ".plot_File_Name" at 5.581,-34.246 h1.14
M12 Stackup:
  lines w0.381: 87.278,53.269 97.69,53.269 122.829,53.269 144.667,53.269 161.173,53.269 175.647,53.269 ; 87.278,56.317 97.69,56.317 122.829,56.317 144.667,56.317 161.173,56.317 175.647,56.317 ; 87.278,59.365 97.69,59.365 122.829,59.365 144.667,59.365 161.173,59.365 175.647,59.365 ; 87.278,62.413 97.69,62.413 122.829,62.413 144.667,62.413 161.173,62.413 175.647,62.413 ; 87.278,65.461 97.69,65.461 122.829,65.461 144.667,65.461 161.173,65.461 175.647,65.461 ; 87.278,68.509 97.69,68.509 122.829,68.509 144.667,68.509 161.173,68.509 175.647,68.509 ; 87.278,71.557 97.69,71.557 122.829,71.557 144.667,71.557 161.173,71.557 175.647,71.557 ; 87.278,74.605 97.69,74.605 122.829,74.605 144.667,74.605 161.173,74.605 175.647,74.605 ; 87.278,77.653 97.69,77.653 122.829,77.653 144.667,77.653 161.173,77.653 175.647,77.653 ; 87.278,80.701 175.647,80.701 ; 97.69,83.749 97.69,50.221 ; 122.829,83.749 122.829,50.221 ; 144.667,83.749 144.667,50.221 ; 161.173,83.749 161.173,50.221 ; 175.723,54.808 179.584,54.808 ; 175.723,60.797 179.584,60.797 ; 175.723,67 179.584,67 ; 175.723,72.989 179.584,72.989 ; 178.728,53.952 179.584,54.808 ; 178.728,55.664 179.584,54.808 ; 178.728,59.941 179.584,60.797 ; 178.728,61.653 179.584,60.797 ; 178.728,66.144 179.584,67 ; 178.728,67.856 179.584,67 ; 178.728,72.133 179.584,72.989 ; 178.728,73.845 179.584,72.989 ; 97.69,50.221 87.278,50.221 87.278,83.749 175.647,83.749 175.647,50.221 161.173,50.221 ; 97.69,50.221 122.829,50.221 ; 122.829,50.221 144.667,50.221 ; 144.667,50.221 161.173,50.221
  text "STACK UP:" at 87.433,85.107 h2.16
  text "Layer" at 89.056,81.463 h1.52
  text "Name" at 99.468,81.463 h1.52
  text "Material" at 124.607,81.463 h1.52
  text "Thickness" at 146.445,81.463 h1.52
  text "Constant" at 162.951,81.463 h1.52
  text "Top Overlay" at 99.468,78.415 h1.52
  text "Top Solder" at 99.468,75.367 h1.52
  text "Solder Resist" at 124.607,75.367 h1.52
  text "0.40mil" at 146.445,75.367 h1.52
  text "3.5" at 162.951,75.367 h1.52
  text "2oZ (Copper+Plating)" at 180.303,72.371 h1.52
  text "1" at 89.056,72.319 h1.52
  text "L1-Top Layer" at 99.468,72.319 h1.52
  text "Copper" at 124.607,72.319 h1.52
  text "2.80mil" at 146.445,72.319 h1.52
  text "Dielectric 3" at 99.468,69.271 h1.52
  text "FR-4 High Tg" at 124.607,69.271 h1.52
  text "16.00mil" at 146.445,69.271 h1.52
  text "4.2" at 162.951,69.271 h1.52
  text "2oZ" at 180.303,66.383 h1.52
  text "2" at 89.056,66.223 h1.52
  text "L2-GND1" at 99.468,66.223 h1.52
  text "Copper" at 124.607,66.223 h1.52
  text "2.80mil" at 146.445,66.223 h1.52
  text "Dielectric 2" at 99.468,63.175 h1.52
  text "FR-4 High Tg" at 124.607,63.175 h1.52
  text "18.00mil" at 146.445,63.175 h1.52
  text "4.2" at 162.951,63.175 h1.52
  text "2oZ" at 180.303,60.179 h1.52
  text "3" at 89.056,60.127 h1.52
  text "L3-PWR/SIG" at 99.468,60.127 h1.52
  text "Copper" at 124.607,60.127 h1.52
  text "2.80mil" at 146.445,60.127 h1.52
  text "Dielectric1" at 99.468,57.079 h1.52
  text "FR-4 High Tg" at 124.607,57.079 h1.52
  text "16.00mil" at 146.445,57.079 h1.52
  text "4.2" at 162.951,57.079 h1.52
  text "2oZ (Copper+Plating)" at 180.303,54.191 h1.52
  text "4" at 89.056,54.031 h1.52
  text "L4-Bottom Layer" at 99.468,54.031 h1.52
  text "Copper" at 124.607,54.031 h1.52
  text "2.80mil" at 146.445,54.031 h1.52
  text "Bottom Solder" at 99.468,50.983 h1.52
  text "Solder Resist" at 124.607,50.983 h1.52
  text "0.40mil" at 146.445,50.983 h1.52
  text "3.5" at 162.951,50.983 h1.52
  text ".Layer_Name" at 9.082,-28.565 h1.52
M13 Component Bodies Top:
  text ".Layer_Name" at 9.082,-28.565 h1.52
M14 Component Bodies Bottom:
  text ".Layer_Name" at 9.082,-28.565 h1.52
M15 Courtyards Top:
  text ".Layer_Name" at 9.082,-28.565 h1.52
M16 Courtyards Bottom:
  text ".Layer_Name" at 9.082,-28.565 h1.52
Drill Drawing:
  circle w0.254: c90.083,11.002 r0.847
  lines w0.254: 89.237,6.768 89.66,6.768 90.083,6.345 90.507,6.768 90.93,6.768 90.507,7.192 90.93,7.615 90.507,7.615 90.083,8.038 89.66,7.615 89.237,7.615 89.66,7.192 89.237,6.768 ; 89.237,13.965 89.237,14.388 89.66,14.812 89.237,15.235 89.237,15.658 89.66,15.658 90.083,15.235 90.507,15.658 90.93,15.658 90.93,15.235 90.507,14.812 90.93,14.388 90.93,13.965 90.507,13.965 90.083,14.388 89.66,13.965 89.237,13.965 ; 89.237,18.622 90.083,17.775 90.93,18.622 90.083,19.468 89.237,18.622 ; 89.237,21.585 90.083,22.008 90.93,21.585 90.507,22.432 90.93,23.278 90.083,22.855 89.237,23.278 89.66,22.432 89.237,21.585 ; 89.237,25.395 90.93,25.395 90.93,27.088 89.237,27.088 89.237,25.395 ; 89.237,29.205 90.93,29.205 90.93,30.898 89.237,30.898 89.237,29.205 ; 89.237,33.438 89.66,33.438 89.66,33.015 90.507,33.015 90.507,33.438 90.93,33.438 90.93,34.285 90.507,34.285 90.507,34.708 89.66,34.708 89.66,34.285 89.237,34.285 89.237,33.438 ; 89.575,25.734 90.591,25.734 90.591,26.75 89.575,26.75 89.575,25.734
  lines w0.305: 87.718,5.202 259.171,5.202 ; 87.718,35.682 259.171,35.682 ; 101.71,1.392 101.71,39.492 ; 117.911,1.392 117.911,39.492 ; 152.09,1.392 152.09,39.492 ; 164.939,1.392 164.939,39.492 ; 183.577,1.392 183.577,39.492 ; 230.553,1.392 230.553,39.492 ; 87.718,1.392 259.171,1.392 259.171,39.492 87.718,39.492 87.718,1.392
  text "DRILL TABLE:" at 87.339,41.376 h2.16
  text "Symbol" at 90.004,36.825 h1.83
  text "Quantity" at 102.853,36.825 h1.83
  text "Finished Hole Size" at 119.054,36.825 h1.83
  text "Plated" at 153.233,36.825 h1.83
  text "Hole Type" at 166.082,36.825 h1.83
  text "Drill Layer Pair" at 184.72,36.825 h1.83
  text "Hole Tolerance" at 231.696,36.825 h1.83
  text "11" at 102.853,33.015 h1.52
  text "7.87mil (0.200mm)" at 119.054,33.015 h1.52
  text "PTH" at 153.233,33.015 h1.52
  text "Round" at 166.082,33.015 h1.52
  text "L1-Top Layer - L4-Bottom Layer" at 184.72,33.015 h1.52
  text "+3mil/-3mil" at 231.696,33.015 h1.52
  text "257" at 102.853,29.205 h1.52
  text "12.00mil (0.305mm)" at 119.054,29.205 h1.52
  text "PTH" at 153.233,29.205 h1.52
  text "Round" at 166.082,29.205 h1.52
  text "L1-Top Layer - L4-Bottom Layer" at 184.72,29.205 h1.52
  text "+3mil/-3mil" at 231.696,29.205 h1.52
  text "12" at 102.853,25.395 h1.52
  text "16.00mil (0.406mm)" at 119.054,25.395 h1.52
  text "PTH" at 153.233,25.395 h1.52
  text "Round" at 166.082,25.395 h1.52
  text "L1-Top Layer - L4-Bottom Layer" at 184.72,25.395 h1.52
  text "+3mil/-3mil" at 231.696,25.395 h1.52
  text "39" at 102.853,21.585 h1.52
  text "40.00mil (1.016mm)" at 119.054,21.585 h1.52
  text "PTH" at 153.233,21.585 h1.52
  text "Round" at 166.082,21.585 h1.52
  text "L1-Top Layer - L4-Bottom Layer" at 184.72,21.585 h1.52
  text "+3mil/-3mil" at 231.696,21.585 h1.52
  text "2" at 102.853,17.775 h1.52
  text "41.34mil (1.050mm)" at 119.054,17.775 h1.52
  text "PTH" at 153.233,17.775 h1.52
  text "Round" at 166.082,17.775 h1.52
  text "L1-Top Layer - L4-Bottom Layer" at 184.72,17.775 h1.52
  text "+3mil/-3mil" at 231.696,17.775 h1.52
  text "17" at 102.853,13.965 h1.52
  text "63.00mil (1.600mm)" at 119.054,13.965 h1.52
  text "PTH" at 153.233,13.965 h1.52
  text "Round" at 166.082,13.965 h1.52
  text "L1-Top Layer - L4-Bottom Layer" at 184.72,13.965 h1.52
  text "+3mil/-3mil" at 231.696,13.965 h1.52
  text "4" at 102.853,10.155 h1.52
  text "125.98mil (3.200mm)" at 119.054,10.155 h1.52
  text "NPTH" at 153.233,10.155 h1.52
  text "Round" at 166.082,10.155 h1.52
  text "L1-Top Layer - L4-Bottom Layer" at 184.72,10.155 h1.52
  text "+2mil/-2mil" at 231.696,10.155 h1.52
  text "4" at 102.853,6.345 h1.52
  text "214.57mil (5.450mm)" at 119.054,6.345 h1.52
  text "PTH" at 153.233,6.345 h1.52
  text "Round" at 166.082,6.345 h1.52
  text "L1-Top Layer - L4-Bottom Layer" at 184.72,6.345 h1.52
  text "+3mil/-3mil" at 231.696,6.345 h1.52
  text "346 Total" at 102.853,2.535 h1.52
  text ".Layer_Name" at 9.082,-28.565 h1.52
M17 Embedded Cavity:
  text ".Layer_Name" at 9.082,-28.565 h1.52
M18 Embedded Assembly:
  text ".Layer_Name" at 9.082,-28.565 h1.52
M19 Embedded Keepout:
  text ".Layer_Name" at 9.082,-28.565 h1.52

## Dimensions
0,0 to 0,78.74 on M2 Board Dimensions
0,78.74 to 76.2,78.74 on M2 Board Dimensions
-5.573,-16.919 to 19.827,-16.919 on M2 Board Dimensions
